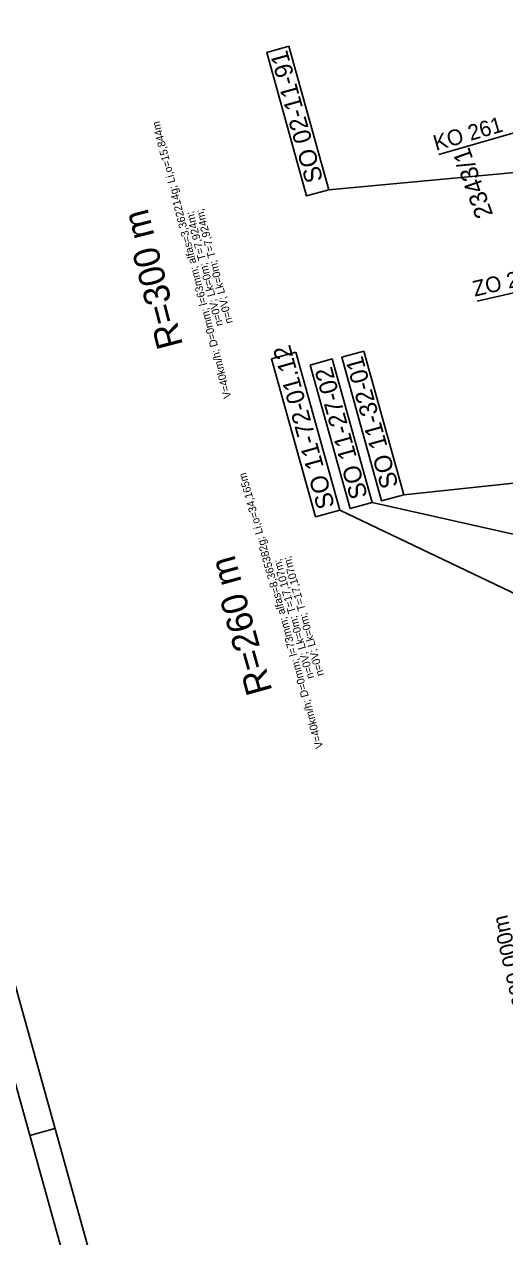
# Model space of a CAD drawing. Extents: x -821057 to -820632, y -1070881 to -1069829.
# Drawn here: x -820888.5 to -820842.4, y -1070485.9 to -1070369.4 of the extents above; entities that cross this region are included whole.
import ezdxf

# ---------------------------------------------------------------- set-up
doc = ezdxf.new("R2010")
doc.units = 0
for name, color, linetype in [('_PS_SO_číslo', 7, 'Continuous'), ('Parcelní čísla', 7, 'Continuous'), ('Rám', 7, 'Continuous'), ('SO-11-10-01', 7, 'Continuous')]:
    doc.layers.add(name, color=color, linetype=linetype)

msp = doc.modelspace()

# ---------------------------------------------------------------- linework, layer by layer
at = {"layer": '_PS_SO_číslo'}
for p, q in [((-820825.63, -1070382.19), (-820859.3, -1070385.32)), ((-820791.02, -1070408.16), (-820852.1, -1070414.6)), ((-820809.59, -1070425.65), (-820855.13, -1070415.34)), ((-820805.22, -1070441.5), (-820858.23, -1070416.07))]:
    msp.add_line(p, q, dxfattribs=at)
for points in [[(-820863.13, -1070371.54), (-820859.3, -1070385.32), (-820861.42, -1070385.91), (-820865.25, -1070372.13)], [(-820862.45, -1070400.91), (-820858.23, -1070416.07), (-820860.57, -1070416.72), (-820864.78, -1070401.56)], [(-820858.96, -1070401.56), (-820855.13, -1070415.34), (-820857.25, -1070415.93), (-820861.08, -1070402.15)], [(-820855.93, -1070400.82), (-820852.1, -1070414.6), (-820854.22, -1070415.19), (-820858.05, -1070401.41)]]:
    msp.add_lwpolyline(points, close=True, dxfattribs=at)
at = {"layer": 'Rám'}
msp.add_line((-820887.98, -1070476.14), (-820885.58, -1070475.47), dxfattribs=at)
for points in [[(-821000.43, -1070071.48), (-820857.35, -1070031.72), (-820632.46, -1070841.06), (-820775.54, -1070880.81)], [(-820997.35, -1070073.22), (-820859.09, -1070034.8), (-820635.54, -1070839.32), (-820773.8, -1070877.73)]]:
    msp.add_lwpolyline(points, close=True, dxfattribs=at)
at = {"layer": 'SO-11-10-01'}
for p, q in [((-820848.74, -1070381.94), (-820824.73, -1070374.99)), ((-820845.05, -1070396.03), (-820820.71, -1070390.32))]:
    msp.add_line(p, q, dxfattribs=at)

# ---------------------------------------------------------------- texts
at = {"layer": '_PS_SO_číslo'}
for s, p in [('SO 02-11-91', (-820859.82, -1070384.37)), ('SO 11-72-01.12', (-820858.7, -1070415.7)), ('SO 11-32-01', (-820852.59, -1070413.73)), ('SO 11-27-02', (-820855.54, -1070414.75))]:
    msp.add_text(s, height=1.7, rotation=105.5289, dxfattribs=at).set_placement(p)
at = {"layer": 'Parcelní čísla'}
msp.add_text('2343/1', height=1.7, rotation=109.6039, dxfattribs=at).set_placement((-820843.5, -1070387.7))
at = {"layer": 'SO-11-10-01'}
for s, height, rotation, p in [('V=40km/h; D=0mm; l=63mm; alfas=3,362214g; Li,o=15,844m', 0.75, 104.5752, (-820868.64, -1070405.25)), ('KO 261 ', 1.5, 16.1416, (-820849, -1070381.59)), ('R=300 m', 2.5, 104.5752, (-820873.27, -1070400.23)), ('n=0V; Lk=0m; T=7,924m;', 0.75, 104.5752, (-820869.44, -1070398.31)), ('n=0V; Lk=0m; T=7,924m;', 0.75, 104.5752, (-820868.5, -1070398.07)), ('ZO 261 ', 1.5, 13.2204, (-820845.28, -1070395.59)), ('V=40km/h; D=0mm; l=73mm; alfas=8,365382g; Li,o=34,165m', 0.75, 105.6858, (-820859.82, -1070438.86)), ('R=260 m', 2.5, 105.6858, (-820864.69, -1070433.43)), ('n=0V; Lk=0m; T=17,107m;', 0.75, 105.6858, (-820860.69, -1070432.17)), ('n=0V; Lk=0m; T=17,107m;', 0.75, 105.6858, (-820859.75, -1070431.91)), ('Rv=2000,000m', 1.5, 103.1891, (-820839.05, -1070468.16))]:
    msp.add_text(s, height=height, rotation=rotation, dxfattribs=at).set_placement(p)

doc.saveas('drawing.dxf')
